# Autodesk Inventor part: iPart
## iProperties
Shininess: 64.0
Length Units: 11269
Angle Units: 11279
Time Units: 11290
Mass Units: 11283
Length Display Precision: 3
Angle Display Precision: 2
Compacted: True
Part Number: iPart
Document SubType Name: Modeling
Created: 2002-11
Designer: ***
Density: 0.0
Volumn: 0.0
Area: 0.0
PropertySet Name: Model Information
Control State: 0
Master: False
Checked Out: False
Author: ***
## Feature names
1. Derived Body1 [Tagging]
